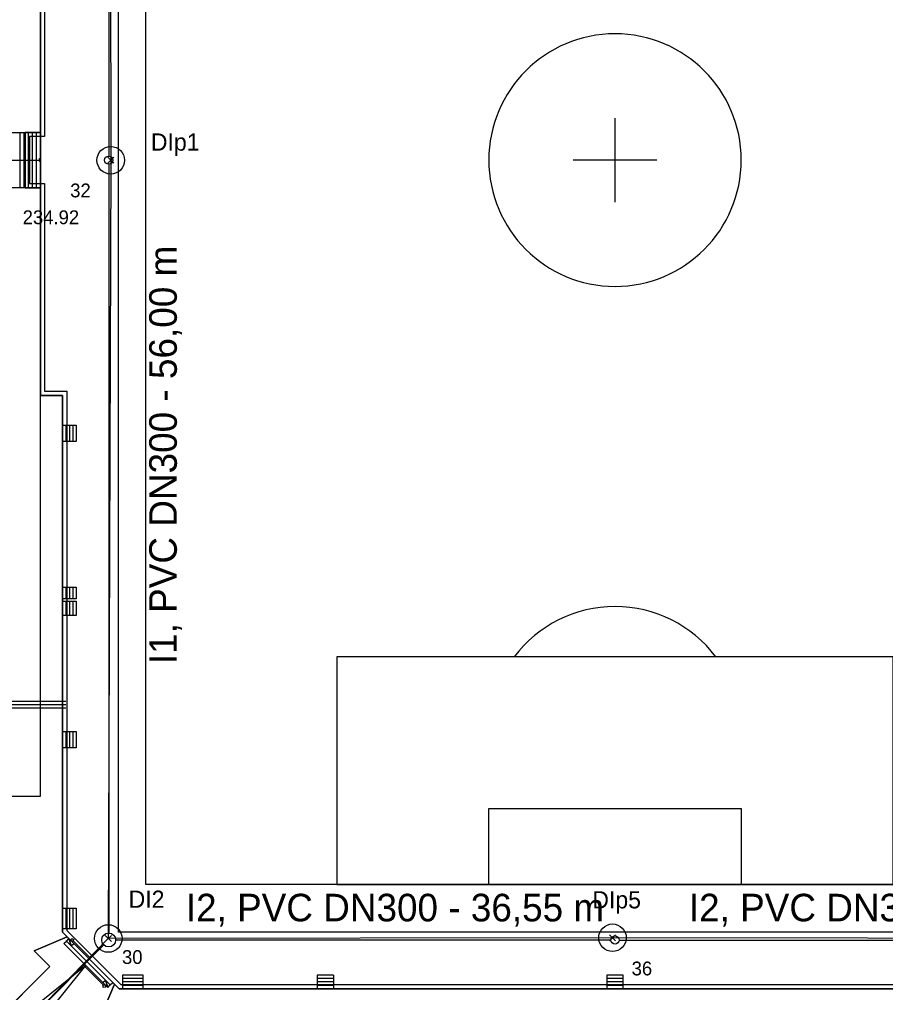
# Model space of a CAD drawing. Extents: x -264234 to -263604, y -1242346 to -1242049.
# Drawn here: x -263895.1 to -263832.4, y -1242224.7 to -1242154.2 of the extents above; entities that cross this region are included whole.
import ezdxf

# ---------------------------------------------------------------- set-up
doc = ezdxf.new("R2010")
doc.units = 0
for name, color, linetype in [('KFA_BODY_CISLO', 7, 'Continuous'), ('KFA_BODY_SYMBOL', 7, 'Continuous'), ('KFA_BODY_VYSKA', 7, 'Continuous'), ('KFA_DAZDOVA_KANALIZACIA_vetva_I', 7, 'Continuous'), ('KFA_DAZDOVA_KANALIZACIA_vetva_I_popis', 7, 'Continuous'), ('KFA_SITUACIA_DSP', 7, 'Continuous')]:
    doc.layers.add(name, color=color, linetype=linetype)

msp = doc.modelspace()

# ---------------------------------------------------------------- linework, layer by layer
at = {"layer": 'KFA_BODY_SYMBOL'}
for p, q in [((-263888.744, -1242164.616), (-263888.302, -1242164.174)), ((-263888.302, -1242164.616), (-263888.744, -1242164.174)), ((-263888.922, -1242221.007), (-263888.48, -1242220.565)), ((-263888.48, -1242221.007), (-263888.922, -1242220.565)), ((-263852.373, -1242220.957), (-263851.931, -1242220.515)), ((-263851.931, -1242220.957), (-263852.373, -1242220.515))]:
    msp.add_line(p, q, dxfattribs=at)
at = {"layer": 'KFA_DAZDOVA_KANALIZACIA_vetva_I'}
for points in [[(-263814.907, -1242107.856), (-263815.198, -1242164.443), (-263815.189, -1242220.791), (-263852.152, -1242220.736), (-263888.701, -1242220.786), (-263906.731, -1242239.259)], [(-263814.907, -1242107.856), (-263851.887, -1242107.945), (-263888.606, -1242107.773), (-263888.523, -1242164.395), (-263888.701, -1242220.786)]]:
    msp.add_lwpolyline(points, dxfattribs=at)
for centre in [(-263888.523, -1242164.395), (-263888.701, -1242220.786), (-263852.152, -1242220.736)]:
    msp.add_circle(centre, 1, dxfattribs=at)
at = {"layer": 'KFA_SITUACIA_DSP'}
for p, q in [((-263888.673, -1242108.177), (-263888.673, -1242164.087)), ((-263851.973, -1242161.342), (-263851.973, -1242167.422)), ((-263895.118, -1242162.382), (-263895.118, -1242166.382)), ((-263894.818, -1242162.382), (-263894.818, -1242166.382)), ((-263894.518, -1242162.382), (-263894.518, -1242166.382)), ((-263894.218, -1242162.382), (-263894.218, -1242166.382)), ((-263893.918, -1242162.382), (-263893.918, -1242166.382)), ((-263893.618, -1242162.382), (-263893.618, -1242166.382)), ((-263898.118, -1242164.382), (-263893.618, -1242164.382)), ((-263893.618, -1242164.382), (-263893.721, -1242164.274)), ((-263893.618, -1242164.382), (-263893.721, -1242164.491)), ((-263848.933, -1242164.382), (-263855.013, -1242164.382)), ((-263888.673, -1242164.687), (-263888.673, -1242220.396)), ((-263892.018, -1242183.583), (-263891.018, -1242183.583)), ((-263891.768, -1242183.583), (-263891.768, -1242184.781)), ((-263891.518, -1242183.583), (-263891.518, -1242184.781)), ((-263891.268, -1242183.583), (-263891.268, -1242184.781)), ((-263891.018, -1242183.583), (-263891.018, -1242184.781)), ((-263891.018, -1242184.781), (-263892.018, -1242184.781)), ((-263892.018, -1242195.333), (-263891.018, -1242195.333)), ((-263891.768, -1242195.333), (-263891.768, -1242196.181)), ((-263891.518, -1242195.333), (-263891.518, -1242196.181)), ((-263891.268, -1242195.333), (-263891.268, -1242196.181)), ((-263891.018, -1242195.333), (-263891.018, -1242196.181)), ((-263891.018, -1242196.181), (-263892.018, -1242196.181)), ((-263892.018, -1242196.333), (-263891.018, -1242196.333)), ((-263891.768, -1242196.333), (-263891.768, -1242197.381)), ((-263891.518, -1242196.333), (-263891.518, -1242197.381)), ((-263891.268, -1242196.333), (-263891.268, -1242197.381)), ((-263891.018, -1242196.333), (-263891.018, -1242197.381)), ((-263891.018, -1242197.381), (-263892.018, -1242197.381)), ((-263892.018, -1242205.783), (-263891.018, -1242205.783)), ((-263891.768, -1242205.783), (-263891.768, -1242206.981)), ((-263891.518, -1242205.783), (-263891.518, -1242206.981)), ((-263891.268, -1242205.783), (-263891.268, -1242206.981)), ((-263891.018, -1242205.783), (-263891.018, -1242206.981)), ((-263891.018, -1242206.981), (-263892.018, -1242206.981)), ((-263892.018, -1242218.593), (-263891.018, -1242218.593)), ((-263891.768, -1242218.593), (-263891.768, -1242220.091)), ((-263891.518, -1242218.593), (-263891.518, -1242220.091)), ((-263891.268, -1242218.593), (-263891.268, -1242220.091)), ((-263891.018, -1242218.593), (-263891.018, -1242220.091)), ((-263891.018, -1242220.091), (-263892.018, -1242220.091)), ((-263891.924, -1242221.157), (-263891.74, -1242220.973)), ((-263891.742, -1242220.974), (-263891.558, -1242220.79)), ((-263888.558, -1242224.155), (-263891.74, -1242220.973)), ((-263891.558, -1242220.79), (-263891.204, -1242221.144)), ((-263888.376, -1242223.973), (-263891.558, -1242220.79)), ((-263891.387, -1242221.326), (-263891.558, -1242220.79)), ((-263891.24, -1242220.967), (-263889.988, -1242222.219)), ((-263852.268, -1242220.896), (-263888.173, -1242220.896)), ((-263851.668, -1242220.896), (-263815.763, -1242220.896)), ((-263889.023, -1242221.253), (-263906.365, -1242238.596)), ((-263891.924, -1242221.157), (-263888.742, -1242224.339)), ((-263891.388, -1242221.328), (-263891.204, -1242221.144)), ((-263889.059, -1242224.16), (-263890.494, -1242222.725)), ((-263889.096, -1242223.985), (-263888.912, -1242223.801)), ((-263888.742, -1242224.339), (-263888.912, -1242223.801)), ((-263886.179, -1242223.432), (-263887.677, -1242223.432)), ((-263887.677, -1242223.432), (-263887.677, -1242224.432)), ((-263886.179, -1242223.682), (-263887.677, -1242223.682)), ((-263886.179, -1242224.432), (-263886.179, -1242223.432)), ((-263872.369, -1242223.432), (-263873.567, -1242223.432)), ((-263873.567, -1242223.432), (-263873.567, -1242224.432)), ((-263872.369, -1242223.682), (-263873.567, -1242223.682)), ((-263872.369, -1242223.432), (-263872.369, -1242224.432)), ((-263851.369, -1242223.432), (-263852.567, -1242223.432)), ((-263852.567, -1242223.432), (-263852.567, -1242224.432)), ((-263851.369, -1242223.682), (-263852.567, -1242223.682)), ((-263851.369, -1242224.432), (-263851.369, -1242223.432)), ((-263888.742, -1242224.339), (-263888.558, -1242224.155)), ((-263888.56, -1242224.156), (-263888.376, -1242223.973)), ((-263886.179, -1242223.932), (-263887.677, -1242223.932)), ((-263886.179, -1242224.182), (-263887.677, -1242224.182)), ((-263872.369, -1242223.932), (-263873.567, -1242223.932)), ((-263872.369, -1242224.182), (-263873.567, -1242224.182)), ((-263851.369, -1242223.932), (-263852.567, -1242223.932)), ((-263851.369, -1242224.182), (-263852.567, -1242224.182))]:
    msp.add_line(p, q, dxfattribs=at)
for points in [[(-263816.02, -1242224.432), (-263811.918, -1242220.33), (-263811.918, -1242108.434), (-263816.02, -1242104.332), (-263887.916, -1242104.332), (-263892.018, -1242108.434), (-263892.018, -1242147.332), (-263893.618, -1242147.332), (-263893.618, -1242162.382), (-263894.718, -1242162.382), (-263894.718, -1242166.382), (-263893.618, -1242166.382), (-263893.618, -1242181.432), (-263892.018, -1242181.432), (-263892.018, -1242220.33), (-263887.916, -1242224.432)], [(-263816.144, -1242224.132), (-263812.218, -1242220.206), (-263812.218, -1242108.558), (-263816.144, -1242104.632), (-263887.792, -1242104.632), (-263891.718, -1242108.558), (-263891.718, -1242147.632), (-263893.318, -1242147.632), (-263893.318, -1242162.682), (-263894.418, -1242162.682), (-263894.418, -1242166.082), (-263893.318, -1242166.082), (-263893.318, -1242181.132), (-263891.718, -1242181.132), (-263891.718, -1242220.206), (-263887.792, -1242224.132)], [(-263887.968, -1242108.434), (-263815.968, -1242108.434), (-263815.968, -1242220.33), (-263887.968, -1242220.33)], [(-263885.968, -1242111.882), (-263817.968, -1242111.882), (-263817.968, -1242216.882), (-263885.968, -1242216.882)], [(-263893.618, -1242118.282), (-263916.093, -1242118.282), (-263916.093, -1242175.482), (-263914.293, -1242175.482), (-263914.293, -1242210.482), (-263893.618, -1242210.482), (-263893.618, -1242166.382), (-263900.043, -1242166.382), (-263900.043, -1242162.382), (-263893.618, -1242162.382)], [(-263831.808, -1242200.382), (-263872.128, -1242200.382), (-263872.128, -1242216.882), (-263831.808, -1242216.882)], [(-263842.808, -1242211.382), (-263861.128, -1242211.382), (-263861.128, -1242216.882), (-263842.808, -1242216.882)], [(-263891.558, -1242220.79), (-263891.387, -1242221.326), (-263891.204, -1242221.144)], [(-263888.742, -1242224.339), (-263888.558, -1242224.155), (-263888.912, -1242223.801)]]:
    msp.add_lwpolyline(points, close=True, dxfattribs=at)
for points in [[(-263811.918, -1242108.434), (-263811.918, -1242220.33), (-263812.262, -1242220.675), (-263809.862, -1242221.669), (-263810.999, -1242222.806), (-263807.039, -1242226.765), (-263809.585, -1242229.311), (-263813.545, -1242225.351), (-263814.681, -1242226.488), (-263815.675, -1242224.088), (-263816.02, -1242224.432), (-263887.916, -1242224.432), (-263888.26, -1242224.088), (-263889.254, -1242226.488), (-263890.391, -1242225.351), (-263894.351, -1242229.311), (-263896.896, -1242226.765), (-263892.937, -1242222.806), (-263894.073, -1242221.669), (-263891.673, -1242220.675), (-263892.018, -1242220.33), (-263892.018, -1242181.432), (-263893.618, -1242181.432), (-263893.618, -1242147.332)], [(-263918.593, -1242164.382), (-263914.35, -1242168.625), (-263914.35, -1242199.59), (-263910.108, -1242203.832), (-263891.768, -1242203.832)], [(-263918.489, -1242164.132), (-263914.1, -1242168.521), (-263914.1, -1242199.486), (-263910.004, -1242203.582), (-263891.768, -1242203.582)], [(-263918.696, -1242164.632), (-263914.6, -1242168.728), (-263914.6, -1242199.693), (-263910.211, -1242204.082), (-263891.768, -1242204.082)], [(-263891.673, -1242220.675), (-263894.073, -1242221.669), (-263892.937, -1242222.806), (-263898.544, -1242228.407)], [(-263895.995, -1242230.956), (-263890.391, -1242225.352), (-263889.254, -1242226.488), (-263888.26, -1242224.088), (-263891.673, -1242220.675)], [(-263903.277, -1242233.148), (-263900.731, -1242235.694), (-263890.333, -1242222.748), (-263903.277, -1242233.148)]]:
    msp.add_lwpolyline(points, dxfattribs=at)
for centre, radius in [((-263888.673, -1242164.387), 0.3), ((-263891.31, -1242220.896), 0.1), ((-263888.673, -1242220.896), 0.5), ((-263851.968, -1242220.896), 0.3), ((-263888.988, -1242224.231), 0.1)]:
    msp.add_circle(centre, radius, dxfattribs=at)
for centre, start, end in [((-263851.968, -1242164.382), 0, 180), ((-263851.968, -1242164.382), 180, 0), ((-263851.968, -1242205.882), 36.94821, 143.05179)]:
    msp.add_arc(centre, 9.15, start, end, dxfattribs=at)

# ---------------------------------------------------------------- texts
at = {"layer": 'KFA_BODY_CISLO'}
for s, p in [('32', (-263891.462, -1242167.082)), ('30', (-263887.706, -1242222.632)), ('36', (-263850.763, -1242223.459))]:
    msp.add_text(s, height=1, dxfattribs=at).set_placement(p)
at = {"layer": 'KFA_BODY_VYSKA'}
msp.add_text('234.92', height=1, dxfattribs=at).set_placement((-263894.905, -1242169.026))
at = {"layer": 'KFA_DAZDOVA_KANALIZACIA_vetva_I_popis'}
for s, height, p in [('DIp1', 1.25, (-263885.616, -1242163.699)), ('DI2', 1.25, (-263887.228, -1242218.563)), ('DIp5', 1.25, (-263853.617, -1242218.607)), ('I2, PVC DN300 - 36,55 m', 2, (-263883.082, -1242219.546)), ('I2, PVC DN300 - 36,96 m', 2, (-263846.616, -1242219.546))]:
    msp.add_text(s, height=height, dxfattribs=at).set_placement(p)
msp.add_text('I1, PVC DN300 - 56,00 m', height=2, rotation=90, dxfattribs=at).set_placement((-263883.733, -1242200.909))

doc.saveas('drawing.dxf')
